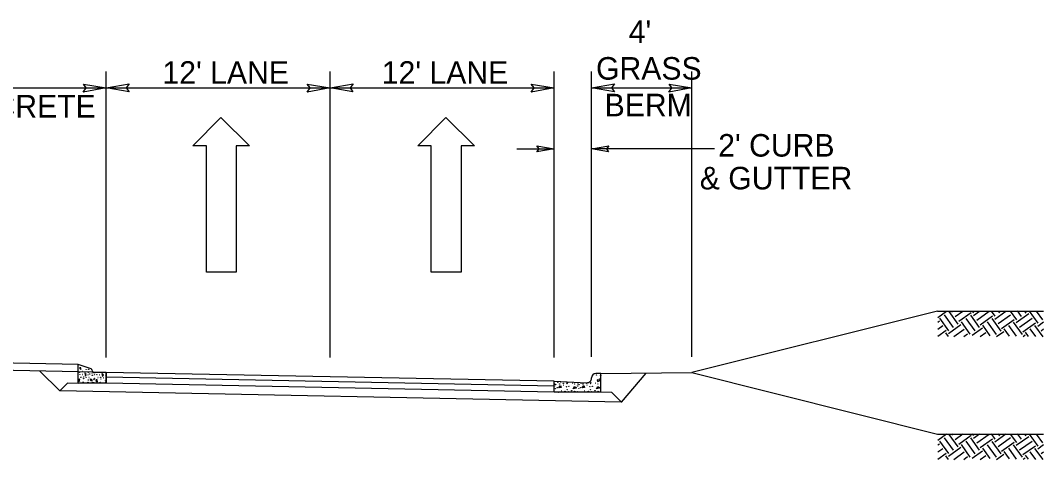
# Model space of a CAD drawing. Extents: x 3025871 to 3026431, y 707165 to 707825.
# Drawn here: x 3026164.7 to 3026219.6, y 707798.2 to 707821.7 of the extents above; entities that cross this region are included whole.
import ezdxf

# ---------------------------------------------------------------- set-up
doc = ezdxf.new("R2010")
doc.units = 0
for name, color, linetype in [('Prop Drainage Structure Junction Box with Manhole CELL', 7, 'Continuous'), ('Prop Drainage Structure Junction Box with Slab Lid TB 840 34 CELL', 7, 'Continuous'), ('Prop Drainage Structure Plot Symbol 50 Scale', 7, 'Continuous'), ('Prop North Arrow for Plan Sheets CELL', 7, 'Continuous'), ('Prop Pavement Schedule Description CELL', 7, 'Continuous'), ('Sheet Data Field CELL', 7, 'Continuous'), ('Sheet Plot Border Inside CELL', 7, 'Continuous'), ('Sheet Typical CELL', 7, 'Continuous'), ('Typical Text Centerline CELL', 7, 'Continuous'), ('Typical Text Grade Point CELL', 7, 'Continuous')]:
    doc.layers.add(name, color=color, linetype=linetype)

msp = doc.modelspace()

# ---------------------------------------------------------------- linework, layer by layer
at = {"layer": 'Prop Drainage Structure Junction Box with Manhole CELL'}
for p, q in [((3026166.848, 707801.881), (3026167.252, 707802.29)), ((3026167.84, 707802.281), (3026167.252, 707802.29)), ((3026196.956, 707801.278), (3026166.848, 707801.881))]:
    msp.add_line(p, q, dxfattribs=at)
at = {"layer": 'Prop Drainage Structure Junction Box with Slab Lid TB 840 34 CELL'}
for p, q in [((3026169.338, 707803.663), (3026169.338, 707819.008)), ((3026181.338, 707803.663), (3026181.338, 707819.008)), ((3026193.346, 707803.663), (3026193.346, 707819.008)), ((3026195.354, 707803.704), (3026195.354, 707819.008)), ((3026200.737, 707803.704), (3026200.737, 707819.008)), ((3026127.83, 707818.116), (3026193.346, 707818.116)), ((3026195.354, 707818.116), (3026200.737, 707818.116)), ((3026191.346, 707814.849), (3026193.346, 707814.849)), ((3026201.955, 707814.847), (3026195.352, 707814.85))]:
    msp.add_line(p, q, dxfattribs=at)
at = {"layer": 'Prop Drainage Structure Plot Symbol 50 Scale'}
for p, q in [((3026167.837, 707802.289), (3026167.837, 707803.289)), ((3026168.523, 707803.06), (3026167.837, 707803.289)), ((3026167.984, 707803.117), (3026167.898, 707803.117)), ((3026167.898, 707803.117), (3026167.979, 707803.031)), ((3026167.979, 707803.031), (3026167.984, 707803.117)), ((3026168.182, 707802.814), (3026168.224, 707802.665)), ((3026168.265, 707802.756), (3026168.182, 707802.814)), ((3026168.224, 707802.665), (3026168.265, 707802.756)), ((3026168.587, 707802.966), (3026168.587, 707802.972)), ((3026169.338, 707802.873), (3026168.681, 707802.872)), ((3026169.102, 707802.799), (3026169.144, 707802.65)), ((3026169.184, 707802.74), (3026169.102, 707802.799)), ((3026169.144, 707802.65), (3026169.184, 707802.74)), ((3026169.338, 707802.873), (3026169.338, 707802.289)), ((3026169.338, 707802.289), (3026169.338, 707802.866)), ((3026195.353, 707802.56), (3026195.353, 707802.57)), ((3026195.854, 707802.811), (3026195.593, 707802.811)), ((3026195.854, 707801.807), (3026195.854, 707802.811)), ((3026169.338, 707802.289), (3026167.837, 707802.289)), ((3026167.925, 707802.498), (3026167.853, 707802.485)), ((3026167.853, 707802.485), (3026167.889, 707802.376)), ((3026167.889, 707802.376), (3026167.925, 707802.498)), ((3026168.49, 707802.525), (3026168.58, 707802.476)), ((3026168.522, 707802.395), (3026168.49, 707802.525)), ((3026168.58, 707802.476), (3026168.522, 707802.395)), ((3026168.845, 707802.483), (3026168.772, 707802.469)), ((3026168.772, 707802.469), (3026168.809, 707802.36)), ((3026168.809, 707802.36), (3026168.845, 707802.483)), ((3026193.346, 707801.807), (3026193.346, 707802.392)), ((3026193.346, 707802.392), (3026195.102, 707802.319)), ((3026193.607, 707802.047), (3026193.694, 707802.168)), ((3026193.728, 707802.054), (3026193.607, 707802.047)), ((3026193.694, 707802.168), (3026193.728, 707802.054)), ((3026194.375, 707801.996), (3026194.438, 707802.111)), ((3026194.541, 707802.036), (3026194.375, 707801.996)), ((3026194.438, 707802.111), (3026194.541, 707802.036)), ((3026194.861, 707802.047), (3026194.947, 707802.168)), ((3026194.982, 707802.054), (3026194.861, 707802.047)), ((3026194.947, 707802.168), (3026194.982, 707802.054)), ((3026195.629, 707801.996), (3026195.691, 707802.111)), ((3026195.795, 707802.036), (3026195.629, 707801.996)), ((3026195.663, 707802.476), (3026195.68, 707802.385)), ((3026195.818, 707802.431), (3026195.663, 707802.476)), ((3026195.68, 707802.385), (3026195.818, 707802.431)), ((3026195.691, 707802.111), (3026195.795, 707802.036)), ((3026195.854, 707801.807), (3026193.346, 707801.807))]:
    msp.add_line(p, q, dxfattribs=at)
for centre, radius in [((3026168.047, 707803.203), 0.00635), ((3026167.912, 707802.878), 0.00635), ((3026167.921, 707802.769), 0.00635), ((3026167.98, 707802.611), 0.00635), ((3026168.07, 707802.756), 0.00635), ((3026168.074, 707802.918), 0.00635), ((3026168.115, 707802.625), 0.00635), ((3026168.192, 707802.869), 0.00635), ((3026168.264, 707803.013), 0.00635), ((3026168.264, 707802.593), 0.00635), ((3026168.359, 707802.738), 0.00635), ((3026168.382, 707802.873), 0.00635), ((3026168.4, 707803.036), 0.00635), ((3026168.409, 707802.598), 0.00635), ((3026168.45, 707802.783), 0.00635), ((3026168.572, 707802.81), 0.00635), ((3026168.594, 707802.711), 0.00635), ((3026168.7, 707802.555), 0.00635), ((3026168.707, 707802.787), 0.00635), ((3026168.723, 707802.758), 0.00635), ((3026168.84, 707802.754), 0.00635), ((3026168.899, 707802.596), 0.00635), ((3026168.99, 707802.74), 0.00635), ((3026169.035, 707802.609), 0.00635), ((3026169.112, 707802.853), 0.00635), ((3026169.184, 707802.578), 0.00635), ((3026169.279, 707802.722), 0.00635), ((3026169.329, 707802.582), 0.00635), ((3026195.623, 707802.734), 0.00805), ((3026195.841, 707802.7), 0.00805), ((3026167.957, 707802.398), 0.00635), ((3026168.102, 707802.358), 0.00635), ((3026168.129, 707802.53), 0.00635), ((3026168.364, 707802.34), 0.00635), ((3026168.377, 707802.462), 0.00635), ((3026168.608, 707802.335), 0.00635), ((3026168.685, 707802.476), 0.00635), ((3026168.685, 707802.322), 0.00635), ((3026168.877, 707802.383), 0.00635), ((3026169.021, 707802.342), 0.00635), ((3026169.048, 707802.514), 0.00635), ((3026169.283, 707802.325), 0.00635), ((3026169.297, 707802.447), 0.00635), ((3026193.362, 707802.145), 0.00805), ((3026193.379, 707802.243), 0.00805), ((3026193.419, 707802.002), 0.00805), ((3026193.436, 707802.208), 0.00805), ((3026193.516, 707802.048), 0.00805), ((3026193.545, 707802.334), 0.00805), ((3026193.642, 707802.248), 0.00805), ((3026193.688, 707802.351), 0.00805), ((3026193.837, 707802.288), 0.00805), ((3026193.865, 707802.185), 0.00805), ((3026194.014, 707802.099), 0.00805), ((3026194.043, 707802.271), 0.00805), ((3026194.06, 707802.322), 0.00805), ((3026194.14, 707802.128), 0.00805), ((3026194.318, 707802.293), 0.00805), ((3026194.438, 707802.243), 0.00805), ((3026194.616, 707802.145), 0.00805), ((3026194.633, 707802.243), 0.00805), ((3026194.673, 707802.002), 0.00805), ((3026194.689, 707802.208), 0.00805), ((3026194.77, 707802.048), 0.00805), ((3026194.798, 707802.291), 0.00805), ((3026194.895, 707802.248), 0.00805), ((3026195.09, 707802.288), 0.00805), ((3026195.119, 707802.185), 0.00805), ((3026195.268, 707802.099), 0.00805), ((3026195.297, 707802.271), 0.00805), ((3026195.314, 707802.322), 0.00805), ((3026195.394, 707802.128), 0.00805), ((3026195.571, 707802.293), 0.00805), ((3026195.692, 707802.243), 0.00805), ((3026195.789, 707802.517), 0.00805), ((3026193.356, 707801.836), 0.00805), ((3026193.567, 707801.813), 0.00805), ((3026193.728, 707801.882), 0.00805), ((3026193.934, 707801.859), 0.00805), ((3026194.049, 707801.945), 0.00805), ((3026194.106, 707801.83), 0.00805), ((3026194.284, 707801.893), 0.00805), ((3026194.455, 707801.853), 0.00805), ((3026194.61, 707801.836), 0.00805), ((3026194.821, 707801.813), 0.00805), ((3026194.981, 707801.882), 0.00805), ((3026195.188, 707801.859), 0.00805), ((3026195.302, 707801.945), 0.00805), ((3026195.36, 707801.83), 0.00805), ((3026195.537, 707801.893), 0.00805), ((3026195.709, 707801.853), 0.00805)]:
    msp.add_circle(centre, radius, dxfattribs=at)
for centre, radius, start, end in [((3026168.494, 707802.971), 0.0938, 0.0196, 71.5846), ((3026168.681, 707802.966), 0.0938, 180.0196, 270.0196), ((3026195.112, 707802.559), 0.24, 267.6155, 0), ((3026195.593, 707802.57), 0.24, 90, 180), ((3026167.871, 707802.295), 0.00635, 27.0581, 154.2612)]:
    msp.add_arc(centre, radius, start, end, dxfattribs=at)
at = {"layer": 'Prop North Arrow for Plan Sheets CELL'}
for p, q in [((3026167.837, 707803.289), (3026160.588, 707803.434)), ((3026167.837, 707802.903), (3026160.595, 707803.047))]:
    msp.add_line(p, q, dxfattribs=at)
at = {"layer": 'Prop Pavement Schedule Description CELL'}
for p, q in [((3026169.338, 707802.873), (3026167.837, 707802.903)), ((3026193.346, 707802.392), (3026169.338, 707802.873)), ((3026169.338, 707802.623), (3026193.346, 707802.142)), ((3026193.346, 707801.809), (3026169.341, 707802.289))]:
    msp.add_line(p, q, dxfattribs=at)
at = {"layer": 'Sheet Data Field CELL'}
for p, q in [((3026173.98, 707815.013), (3026175.479, 707816.536)), ((3026175.479, 707816.536), (3026177.026, 707815.013)), ((3026186.039, 707815.013), (3026187.538, 707816.536)), ((3026187.538, 707816.536), (3026189.085, 707815.013)), ((3026174.705, 707815.013), (3026173.98, 707815.013)), ((3026174.705, 707808.243), (3026174.705, 707815.013)), ((3026177.026, 707815.013), (3026176.301, 707815.013)), ((3026176.301, 707815.013), (3026176.301, 707808.243)), ((3026186.764, 707815.013), (3026186.039, 707815.013)), ((3026186.764, 707808.243), (3026186.764, 707815.013)), ((3026189.085, 707815.013), (3026188.36, 707815.013)), ((3026188.36, 707815.013), (3026188.36, 707808.243)), ((3026176.301, 707808.243), (3026174.705, 707808.243)), ((3026188.36, 707808.243), (3026186.764, 707808.243))]:
    msp.add_line(p, q, dxfattribs=at)
at = {"layer": 'Sheet Plot Border Inside CELL'}
msp.add_line((3026196.439, 707801.795), (3026195.854, 707801.807), dxfattribs=at)
at = {"layer": 'Sheet Typical CELL'}
for p, q in [((3026166.848, 707801.881), (3026165.774, 707802.944)), ((3026195.854, 707802.811), (3026200.737, 707802.858)), ((3026196.956, 707801.278), (3026198.279, 707802.834)), ((3026196.439, 707801.795), (3026196.956, 707801.278))]:
    msp.add_line(p, q, dxfattribs=at)
at = {"layer": 'Typical Text Centerline CELL'}
for points in [[(3026168.112, 707818.327), (3026169.337, 707818.116), (3026168.105, 707817.898), (3026168.261, 707818.116)], [(3026170.561, 707817.905), (3026169.336, 707818.116), (3026170.568, 707818.334), (3026170.412, 707818.116)], [(3026180.113, 707818.327), (3026181.338, 707818.116), (3026180.106, 707817.898), (3026180.263, 707818.116)], [(3026182.563, 707817.905), (3026181.338, 707818.116), (3026182.569, 707818.334), (3026182.413, 707818.116)], [(3026192.121, 707818.327), (3026193.346, 707818.116), (3026192.114, 707817.898), (3026192.271, 707818.116)], [(3026196.579, 707817.905), (3026195.354, 707818.116), (3026196.586, 707818.334), (3026196.429, 707818.116)], [(3026199.511, 707818.327), (3026200.737, 707818.116), (3026199.505, 707817.898), (3026199.661, 707818.116)], [(3026192.429, 707815.007), (3026193.348, 707814.849), (3026192.424, 707814.686), (3026192.541, 707814.849)], [(3026196.268, 707814.691), (3026195.35, 707814.85), (3026196.274, 707815.013), (3026196.156, 707814.849)]]:
    msp.add_lwpolyline(points, close=True, dxfattribs=at)
at = {"layer": 'Typical Text Grade Point CELL'}
for p, q in [((3026213.902, 707806.15), (3026200.737, 707802.858)), ((3026213.902, 707806.15), (3026219.586, 707806.15)), ((3026213.902, 707806.15), (3026219.586, 707806.15)), ((3026213.923, 707805.82), (3026214.383, 707806.151)), ((3026213.923, 707805.82), (3026214.383, 707806.151)), ((3026214.763, 707805.283), (3026214.283, 707805.952)), ((3026214.763, 707805.283), (3026214.283, 707805.952)), ((3026215.014, 707805.464), (3026214.533, 707806.132)), ((3026215.014, 707805.464), (3026214.533, 707806.132)), ((3026214.677, 707806.108), (3026214.737, 707806.152)), ((3026214.677, 707806.108), (3026214.737, 707806.152)), ((3026214.857, 707805.858), (3026215.268, 707806.153)), ((3026214.857, 707805.858), (3026215.268, 707806.153)), ((3026215.037, 707805.607), (3026215.706, 707806.088)), ((3026215.037, 707805.607), (3026215.706, 707806.088)), ((3026216.162, 707805.276), (3026215.682, 707805.944)), ((3026216.162, 707805.276), (3026215.682, 707805.944)), ((3026215.849, 707806.064), (3026215.784, 707806.155)), ((3026215.849, 707806.064), (3026215.784, 707806.155)), ((3026215.826, 707805.92), (3026216.153, 707806.156)), ((3026215.826, 707805.92), (3026216.153, 707806.156)), ((3026216.006, 707805.67), (3026216.674, 707806.15)), ((3026216.006, 707805.67), (3026216.674, 707806.15)), ((3026216.186, 707805.419), (3026216.854, 707805.899)), ((3026216.186, 707805.419), (3026216.854, 707805.899)), ((3026216.998, 707805.876), (3026216.795, 707806.158)), ((3026216.998, 707805.876), (3026216.795, 707806.158)), ((3026216.974, 707805.732), (3026217.569, 707806.16)), ((3026216.974, 707805.732), (3026217.569, 707806.16)), ((3026217.155, 707805.482), (3026217.823, 707805.962)), ((3026217.155, 707805.482), (3026217.823, 707805.962)), ((3026217.249, 707806.056), (3026217.175, 707806.159)), ((3026217.249, 707806.056), (3026217.175, 707806.159)), ((3026218.147, 707805.688), (3026217.815, 707806.15)), ((3026218.147, 707805.688), (3026217.815, 707806.15)), ((3026218.123, 707805.544), (3026218.792, 707806.025)), ((3026218.123, 707805.544), (3026218.792, 707806.025)), ((3026218.397, 707805.868), (3026218.186, 707806.162)), ((3026218.397, 707805.868), (3026218.186, 707806.162)), ((3026218.648, 707806.048), (3026218.575, 707806.15)), ((3026218.648, 707806.048), (3026218.575, 707806.15)), ((3026219.295, 707805.5), (3026218.828, 707806.15)), ((3026219.295, 707805.5), (3026218.828, 707806.15)), ((3026219.546, 707805.68), (3026219.208, 707806.15)), ((3026219.546, 707805.68), (3026219.208, 707806.15)), ((3026213.923, 707805.567), (3026214.009, 707805.628)), ((3026213.923, 707805.567), (3026214.009, 707805.628)), ((3026213.923, 707805.187), (3026214.189, 707805.377)), ((3026213.923, 707805.187), (3026214.189, 707805.377)), ((3026214.512, 707805.103), (3026214.032, 707805.772)), ((3026214.512, 707805.103), (3026214.032, 707805.772)), ((3026214.489, 707804.96), (3026215.157, 707805.44)), ((3026214.489, 707804.96), (3026215.157, 707805.44)), ((3026215.661, 707804.915), (3026215.181, 707805.584)), ((3026215.661, 707804.915), (3026215.181, 707805.584)), ((3026215.912, 707805.095), (3026215.431, 707805.764)), ((3026215.912, 707805.095), (3026215.431, 707805.764)), ((3026216.73, 707804.838), (3026216.33, 707805.396)), ((3026216.73, 707804.838), (3026216.33, 707805.396)), ((3026217.06, 707804.907), (3026216.58, 707805.576)), ((3026217.06, 707804.907), (3026216.58, 707805.576)), ((3026217.311, 707805.087), (3026216.831, 707805.756)), ((3026217.311, 707805.087), (3026216.831, 707805.756)), ((3026217.335, 707805.231), (3026218.003, 707805.711)), ((3026217.335, 707805.231), (3026218.003, 707805.711)), ((3026218.144, 707804.81), (3026217.729, 707805.388)), ((3026218.144, 707804.81), (3026217.729, 707805.388)), ((3026218.46, 707804.899), (3026217.98, 707805.568)), ((3026218.46, 707804.899), (3026217.98, 707805.568)), ((3026218.303, 707805.294), (3026218.972, 707805.774)), ((3026218.303, 707805.294), (3026218.972, 707805.774)), ((3026218.483, 707805.043), (3026219.152, 707805.523)), ((3026218.483, 707805.043), (3026219.152, 707805.523)), ((3026219.558, 707804.781), (3026219.128, 707805.38)), ((3026219.558, 707804.781), (3026219.128, 707805.38)), ((3026219.272, 707805.356), (3026219.586, 707805.582)), ((3026219.272, 707805.356), (3026219.586, 707805.582)), ((3026213.923, 707804.807), (3026214.369, 707805.127)), ((3026213.923, 707804.807), (3026214.369, 707805.127)), ((3026214.484, 707804.79), (3026214.345, 707804.983)), ((3026214.484, 707804.79), (3026214.345, 707804.983)), ((3026214.781, 707804.79), (3026215.337, 707805.189)), ((3026214.781, 707804.79), (3026215.337, 707805.189)), ((3026215.31, 707804.79), (3026215.518, 707804.939)), ((3026215.31, 707804.79), (3026215.518, 707804.939)), ((3026215.757, 707804.858), (3026216.306, 707805.252)), ((3026215.757, 707804.858), (3026216.306, 707805.252)), ((3026216.192, 707804.79), (3026216.486, 707805.001)), ((3026216.192, 707804.79), (3026216.486, 707805.001)), ((3026217.073, 707804.79), (3026217.455, 707805.064)), ((3026217.073, 707804.79), (3026217.455, 707805.064)), ((3026217.759, 707804.817), (3026217.478, 707805.208)), ((3026217.759, 707804.817), (3026217.478, 707805.208)), ((3026218.501, 707804.802), (3026218.603, 707804.876)), ((3026218.501, 707804.802), (3026218.603, 707804.876)), ((3026218.787, 707804.797), (3026218.627, 707805.019)), ((3026218.787, 707804.797), (3026218.627, 707805.019)), ((3026219.173, 707804.789), (3026218.878, 707805.2)), ((3026219.173, 707804.789), (3026218.878, 707805.2)), ((3026219.452, 707805.106), (3026219.586, 707805.202)), ((3026219.452, 707805.106), (3026219.586, 707805.202)), ((3026200.737, 707802.858), (3026213.902, 707799.567)), ((3026213.902, 707799.567), (3026219.586, 707799.567)), ((3026213.902, 707799.567), (3026219.586, 707799.567)), ((3026213.923, 707799.238), (3026214.383, 707799.568)), ((3026213.923, 707799.238), (3026214.383, 707799.568)), ((3026214.763, 707798.701), (3026214.283, 707799.369)), ((3026214.763, 707798.701), (3026214.283, 707799.369)), ((3026215.014, 707798.881), (3026214.533, 707799.549)), ((3026215.014, 707798.881), (3026214.533, 707799.549)), ((3026214.677, 707799.526), (3026214.737, 707799.569)), ((3026214.677, 707799.526), (3026214.737, 707799.569)), ((3026214.857, 707799.275), (3026215.268, 707799.571)), ((3026214.857, 707799.275), (3026215.268, 707799.571)), ((3026215.037, 707799.025), (3026215.706, 707799.505)), ((3026215.037, 707799.025), (3026215.706, 707799.505)), ((3026216.162, 707798.693), (3026215.682, 707799.361)), ((3026216.162, 707798.693), (3026215.682, 707799.361)), ((3026215.849, 707799.481), (3026215.784, 707799.572)), ((3026215.849, 707799.481), (3026215.784, 707799.572)), ((3026215.826, 707799.338), (3026216.153, 707799.573)), ((3026215.826, 707799.338), (3026216.153, 707799.573)), ((3026216.006, 707799.087), (3026216.674, 707799.567)), ((3026216.006, 707799.087), (3026216.674, 707799.567)), ((3026216.186, 707798.837), (3026216.854, 707799.317)), ((3026216.186, 707798.837), (3026216.854, 707799.317)), ((3026216.998, 707799.293), (3026216.795, 707799.575)), ((3026216.998, 707799.293), (3026216.795, 707799.575)), ((3026216.974, 707799.15), (3026217.569, 707799.577)), ((3026216.974, 707799.15), (3026217.569, 707799.577)), ((3026217.155, 707798.899), (3026217.823, 707799.379)), ((3026217.155, 707798.899), (3026217.823, 707799.379)), ((3026217.249, 707799.473), (3026217.175, 707799.576)), ((3026217.249, 707799.473), (3026217.175, 707799.576)), ((3026218.147, 707799.105), (3026217.815, 707799.567)), ((3026218.147, 707799.105), (3026217.815, 707799.567)), ((3026218.123, 707798.962), (3026218.792, 707799.442)), ((3026218.123, 707798.962), (3026218.792, 707799.442)), ((3026218.397, 707799.285), (3026218.186, 707799.579)), ((3026218.397, 707799.285), (3026218.186, 707799.579)), ((3026218.648, 707799.466), (3026218.575, 707799.567)), ((3026218.648, 707799.466), (3026218.575, 707799.567)), ((3026219.295, 707798.917), (3026218.828, 707799.567)), ((3026219.295, 707798.917), (3026218.828, 707799.567)), ((3026219.546, 707799.097), (3026219.208, 707799.567)), ((3026219.546, 707799.097), (3026219.208, 707799.567)), ((3026213.923, 707798.984), (3026214.009, 707799.046)), ((3026213.923, 707798.984), (3026214.009, 707799.046)), ((3026213.923, 707798.604), (3026214.189, 707798.795)), ((3026213.923, 707798.604), (3026214.189, 707798.795)), ((3026214.512, 707798.521), (3026214.032, 707799.189)), ((3026214.512, 707798.521), (3026214.032, 707799.189)), ((3026214.489, 707798.377), (3026215.157, 707798.857)), ((3026214.489, 707798.377), (3026215.157, 707798.857)), ((3026215.661, 707798.333), (3026215.181, 707799.001)), ((3026215.661, 707798.333), (3026215.181, 707799.001)), ((3026215.912, 707798.513), (3026215.431, 707799.181)), ((3026215.912, 707798.513), (3026215.431, 707799.181)), ((3026216.73, 707798.255), (3026216.33, 707798.813)), ((3026216.73, 707798.255), (3026216.33, 707798.813)), ((3026217.06, 707798.325), (3026216.58, 707798.993)), ((3026217.06, 707798.325), (3026216.58, 707798.993)), ((3026217.311, 707798.505), (3026216.831, 707799.173)), ((3026217.311, 707798.505), (3026216.831, 707799.173)), ((3026217.335, 707798.648), (3026218.003, 707799.129)), ((3026217.335, 707798.648), (3026218.003, 707799.129)), ((3026218.144, 707798.227), (3026217.729, 707798.805)), ((3026218.144, 707798.227), (3026217.729, 707798.805)), ((3026218.46, 707798.317), (3026217.98, 707798.985)), ((3026218.46, 707798.317), (3026217.98, 707798.985)), ((3026218.303, 707798.711), (3026218.972, 707799.191)), ((3026218.303, 707798.711), (3026218.972, 707799.191)), ((3026218.483, 707798.46), (3026219.152, 707798.941)), ((3026218.483, 707798.46), (3026219.152, 707798.941)), ((3026219.558, 707798.199), (3026219.128, 707798.797)), ((3026219.558, 707798.199), (3026219.128, 707798.797)), ((3026219.272, 707798.774), (3026219.586, 707799)), ((3026219.272, 707798.774), (3026219.586, 707799)), ((3026213.923, 707798.224), (3026214.369, 707798.544)), ((3026213.923, 707798.224), (3026214.369, 707798.544)), ((3026214.484, 707798.207), (3026214.345, 707798.401)), ((3026214.484, 707798.207), (3026214.345, 707798.401)), ((3026214.781, 707798.207), (3026215.337, 707798.607)), ((3026214.781, 707798.207), (3026215.337, 707798.607)), ((3026215.31, 707798.207), (3026215.518, 707798.356)), ((3026215.31, 707798.207), (3026215.518, 707798.356)), ((3026215.757, 707798.275), (3026216.306, 707798.669)), ((3026215.757, 707798.275), (3026216.306, 707798.669)), ((3026216.192, 707798.207), (3026216.486, 707798.419)), ((3026216.192, 707798.207), (3026216.486, 707798.419)), ((3026217.073, 707798.207), (3026217.455, 707798.481)), ((3026217.073, 707798.207), (3026217.455, 707798.481)), ((3026217.759, 707798.235), (3026217.478, 707798.625)), ((3026217.759, 707798.235), (3026217.478, 707798.625)), ((3026218.501, 707798.22), (3026218.603, 707798.293)), ((3026218.501, 707798.22), (3026218.603, 707798.293)), ((3026218.787, 707798.214), (3026218.627, 707798.437)), ((3026218.787, 707798.214), (3026218.627, 707798.437)), ((3026219.173, 707798.206), (3026218.878, 707798.617)), ((3026219.173, 707798.206), (3026218.878, 707798.617)), ((3026219.452, 707798.523), (3026219.586, 707798.619)), ((3026219.452, 707798.523), (3026219.586, 707798.619))]:
    msp.add_line(p, q, dxfattribs=at)

# ---------------------------------------------------------------- texts
at = {"layer": 'Prop Drainage Structure Junction Box with Slab Lid TB 840 34 CELL'}
for s, height, p in [("4'", 1.2089, (3026197.347, 707820.526)), ("12' LANE", 1.2089, (3026172.354, 707818.342)), ("12' LANE", 1.2089, (3026184.111, 707818.342)), ('GRASS', 1.2089, (3026195.596, 707818.562)), ('RAISED CONCRETE', 1.20892, (3026153.235, 707816.532)), ('BERM', 1.2089, (3026196.058, 707816.597)), ("2' CURB", 1.2089, (3026202.144, 707814.437)), ('& GUTTER', 1.2089, (3026201.158, 707812.68))]:
    msp.add_text(s, height=height, dxfattribs=at).set_placement(p)

doc.saveas('drawing.dxf')
